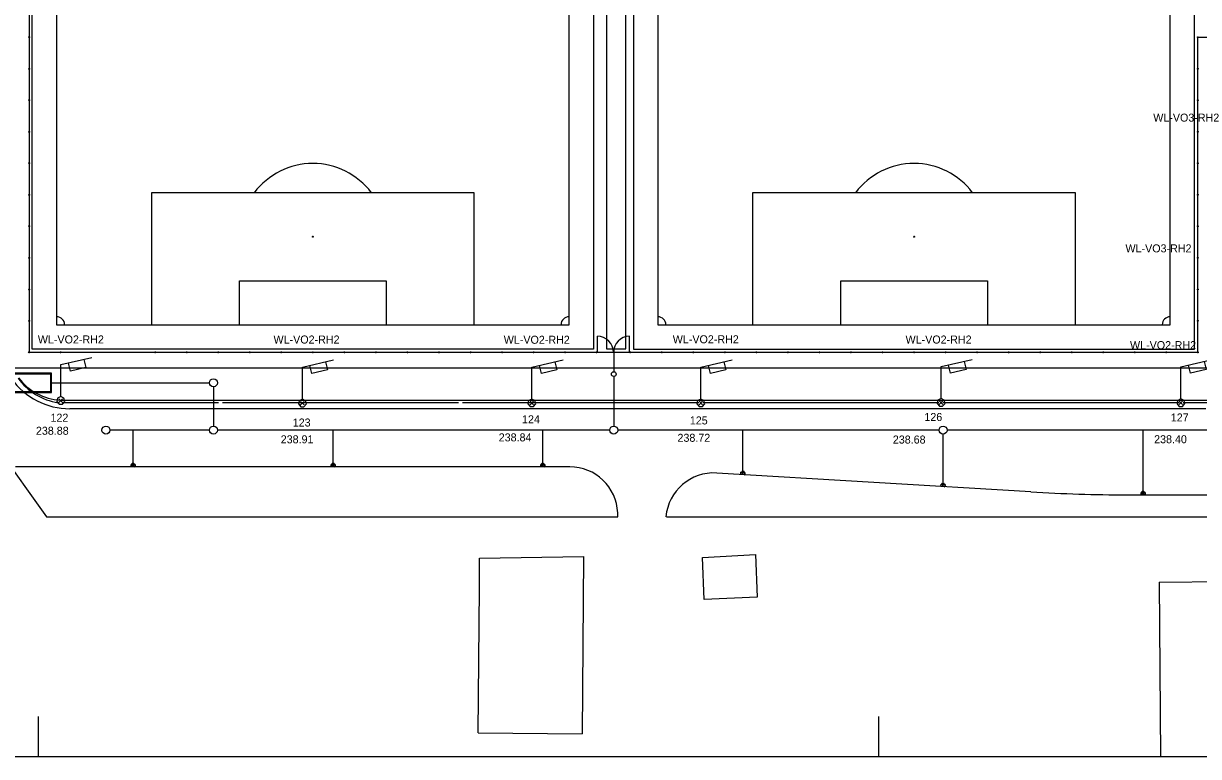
# Model space of a CAD drawing. Extents: x -264222 to -263592, y -1242345 to -1242048.
# Drawn here: x -264118.8 to -263972, y -1242344.9 to -1242253.3 of the extents above; entities that cross this region are included whole.
import ezdxf

# ---------------------------------------------------------------- set-up
doc = ezdxf.new("R2010")
doc.units = 0
for name, color, linetype in [('BOD_CISLO', 7, 'Continuous'), ('BOD_SYMBOL', 7, 'Continuous'), ('BOD_VYSKA', 7, 'Continuous'), ('KFA_2D_SITUACIA_DSP', 7, 'Continuous'), ('KFA_SO_62-1_VO_LAMPY_MERANE', 7, 'Continuous'), ('KFA_SO_62-1_VO_POPIS_LAMP_PROJEKT', 7, 'Continuous'), ('KFA_SO_62-1_VO_TRASA_KABLOV_PROJEKT', 7, 'Continuous'), ('RAM_NA_TLAC_1-500', 7, 'Continuous')]:
    doc.layers.add(name, color=color, linetype=linetype)

msp = doc.modelspace()

# ---------------------------------------------------------------- linework, layer by layer
at = {"layer": 'BOD_SYMBOL'}
for p, q in [((-264114.33, -1242300.69), (-264113.89, -1242300.25)), ((-264113.89, -1242300.69), (-264114.33, -1242300.25)), ((-264084.15, -1242301), (-264083.71, -1242300.56)), ((-264083.71, -1242301), (-264084.15, -1242300.56)), ((-264055.49, -1242300.99), (-264055.05, -1242300.55)), ((-264055.05, -1242300.99), (-264055.49, -1242300.55)), ((-264034.38, -1242300.99), (-264033.94, -1242300.54)), ((-264033.94, -1242300.99), (-264034.38, -1242300.54)), ((-264004.37, -1242300.94), (-264003.92, -1242300.5)), ((-264003.92, -1242300.94), (-264004.37, -1242300.5)), ((-263974.41, -1242300.96), (-263973.97, -1242300.52)), ((-263973.97, -1242300.96), (-263974.41, -1242300.52))]:
    msp.add_line(p, q, dxfattribs=at)
at = {"layer": 'KFA_2D_SITUACIA_DSP'}
for p, q in [((-264118.07, -1242187.53), (-264118.07, -1242294.43)), ((-264204.69, -1242191.48), (-264115.87, -1242314.98)), ((-264114.62, -1242190.98), (-264114.62, -1242290.98)), ((-264050.62, -1242290.98), (-264050.62, -1242190.98)), ((-264039.52, -1242190.98), (-264039.52, -1242290.98)), ((-263975.52, -1242290.98), (-263975.52, -1242190.98)), ((-264045.93, -1242194.98), (-264045.93, -1242293.98)), ((-264043.53, -1242293.98), (-264043.53, -1242194.98)), ((-264118.01, -1242255.06), (-264118.13, -1242255.06)), ((-264118.07, -1242255.12), (-264118.07, -1242255)), ((-263972.13, -1242255.06), (-263972.01, -1242255.06)), ((-263972.07, -1242255.12), (-263972.07, -1242255)), ((-263972.07, -1242255.06), (-263967.42, -1242255.06)), ((-263972.07, -1242294.43), (-263972.07, -1242255.06)), ((-264118.01, -1242258.99), (-264118.13, -1242258.99)), ((-264118.07, -1242259.05), (-264118.07, -1242258.93)), ((-263972.13, -1242258.99), (-263972.01, -1242258.99)), ((-263972.07, -1242259.05), (-263972.07, -1242258.93)), ((-264118.01, -1242262.93), (-264118.13, -1242262.93)), ((-264118.07, -1242262.99), (-264118.07, -1242262.87)), ((-263972.13, -1242262.93), (-263972.01, -1242262.93)), ((-263972.07, -1242262.99), (-263972.07, -1242262.87)), ((-264118.07, -1242266.93), (-264118.07, -1242266.81)), ((-263972.07, -1242266.93), (-263972.07, -1242266.81)), ((-264118.01, -1242266.87), (-264118.13, -1242266.87)), ((-263972.13, -1242266.87), (-263972.01, -1242266.87)), ((-264118.01, -1242270.81), (-264118.13, -1242270.81)), ((-264118.07, -1242270.87), (-264118.07, -1242270.75)), ((-263972.13, -1242270.81), (-263972.01, -1242270.81)), ((-263972.07, -1242270.87), (-263972.07, -1242270.75)), ((-264118.01, -1242274.74), (-264118.13, -1242274.74)), ((-264118.07, -1242274.8), (-264118.07, -1242274.68)), ((-264062.46, -1242274.48), (-264102.78, -1242274.48)), ((-264102.78, -1242274.48), (-264102.78, -1242290.98)), ((-264062.46, -1242290.98), (-264062.46, -1242274.48)), ((-263987.36, -1242274.48), (-264027.68, -1242274.48)), ((-264027.68, -1242274.48), (-264027.68, -1242290.98)), ((-263987.36, -1242290.98), (-263987.36, -1242274.48)), ((-263972.13, -1242274.74), (-263972.01, -1242274.74)), ((-263972.07, -1242274.8), (-263972.07, -1242274.68)), ((-264118.01, -1242278.68), (-264118.13, -1242278.68)), ((-264118.07, -1242278.74), (-264118.07, -1242278.62)), ((-263972.13, -1242278.68), (-263972.01, -1242278.68)), ((-263972.07, -1242278.74), (-263972.07, -1242278.62)), ((-264118.01, -1242282.62), (-264118.13, -1242282.62)), ((-264118.07, -1242282.68), (-264118.07, -1242282.56)), ((-263972.13, -1242282.62), (-263972.01, -1242282.62)), ((-263972.07, -1242282.68), (-263972.07, -1242282.56)), ((-264091.78, -1242290.98), (-264091.78, -1242285.48)), ((-264091.78, -1242285.48), (-264073.46, -1242285.48)), ((-264073.46, -1242285.48), (-264073.46, -1242290.98)), ((-264016.68, -1242290.98), (-264016.68, -1242285.48)), ((-264016.68, -1242285.48), (-263998.36, -1242285.48)), ((-263998.36, -1242285.48), (-263998.36, -1242290.98)), ((-264118.01, -1242286.56), (-264118.13, -1242286.56)), ((-264118.07, -1242286.62), (-264118.07, -1242286.5)), ((-263972.13, -1242286.56), (-263972.01, -1242286.56)), ((-263972.07, -1242286.62), (-263972.07, -1242286.5)), ((-264118.01, -1242290.49), (-264118.13, -1242290.49)), ((-264118.07, -1242290.55), (-264118.07, -1242290.43)), ((-264114.62, -1242290.98), (-264050.62, -1242290.98)), ((-264039.52, -1242290.98), (-263975.52, -1242290.98)), ((-263972.13, -1242290.49), (-263972.01, -1242290.49)), ((-263972.07, -1242290.55), (-263972.07, -1242290.43)), ((-264047.07, -1242294.43), (-264047.07, -1242292.43)), ((-264043.07, -1242294.43), (-264043.07, -1242292.43)), ((-264118.01, -1242294.43), (-264118.13, -1242294.43)), ((-264118.07, -1242294.49), (-264118.07, -1242294.37)), ((-264118.07, -1242294.43), (-264045.12, -1242294.43)), ((-264114.07, -1242294.43), (-264114.19, -1242294.43)), ((-264114.13, -1242294.49), (-264114.13, -1242294.37)), ((-264102.25, -1242294.43), (-264102.37, -1242294.43)), ((-264102.31, -1242294.49), (-264102.31, -1242294.37)), ((-264098.31, -1242294.43), (-264098.43, -1242294.43)), ((-264098.37, -1242294.49), (-264098.37, -1242294.37)), ((-264094.37, -1242294.43), (-264094.49, -1242294.43)), ((-264094.43, -1242294.49), (-264094.43, -1242294.37)), ((-264090.44, -1242294.43), (-264090.56, -1242294.43)), ((-264090.5, -1242294.49), (-264090.5, -1242294.37)), ((-264086.5, -1242294.43), (-264086.62, -1242294.43)), ((-264086.56, -1242294.49), (-264086.56, -1242294.37)), ((-264082.56, -1242294.43), (-264082.68, -1242294.43)), ((-264082.62, -1242294.49), (-264082.62, -1242294.37)), ((-264078.62, -1242294.43), (-264078.74, -1242294.43)), ((-264078.68, -1242294.49), (-264078.68, -1242294.37)), ((-264074.68, -1242294.43), (-264074.8, -1242294.43)), ((-264074.74, -1242294.49), (-264074.74, -1242294.37)), ((-264070.74, -1242294.43), (-264070.86, -1242294.43)), ((-264070.8, -1242294.49), (-264070.8, -1242294.37)), ((-264066.8, -1242294.43), (-264066.92, -1242294.43)), ((-264066.86, -1242294.49), (-264066.86, -1242294.37)), ((-264062.86, -1242294.43), (-264062.98, -1242294.43)), ((-264062.92, -1242294.49), (-264062.92, -1242294.37)), ((-264058.92, -1242294.43), (-264059.04, -1242294.43)), ((-264058.98, -1242294.49), (-264058.98, -1242294.37)), ((-264054.99, -1242294.43), (-264055.11, -1242294.43)), ((-264055.05, -1242294.49), (-264055.05, -1242294.37)), ((-264051.05, -1242294.43), (-264051.17, -1242294.43)), ((-264051.11, -1242294.49), (-264051.11, -1242294.37)), ((-264047.11, -1242294.43), (-264047.23, -1242294.43)), ((-264047.17, -1242294.49), (-264047.17, -1242294.37)), ((-264045.93, -1242293.98), (-264043.53, -1242293.98)), ((-264045.57, -1242294.43), (-264044.57, -1242294.43)), ((-264045.12, -1242294.43), (-263972.07, -1242294.43)), ((-264045.02, -1242293.98), (-264045.03, -1242296.85)), ((-264042.91, -1242294.43), (-264043.03, -1242294.43)), ((-264042.97, -1242294.49), (-264042.97, -1242294.37)), ((-264038.97, -1242294.43), (-264039.09, -1242294.43)), ((-264039.03, -1242294.49), (-264039.03, -1242294.37)), ((-264035.03, -1242294.43), (-264035.15, -1242294.43)), ((-264035.09, -1242294.49), (-264035.09, -1242294.37)), ((-264031.09, -1242294.43), (-264031.21, -1242294.43)), ((-264031.15, -1242294.49), (-264031.15, -1242294.37)), ((-264027.15, -1242294.43), (-264027.27, -1242294.43)), ((-264027.21, -1242294.49), (-264027.21, -1242294.37)), ((-264023.21, -1242294.43), (-264023.33, -1242294.43)), ((-264023.27, -1242294.49), (-264023.27, -1242294.37)), ((-264019.27, -1242294.43), (-264019.39, -1242294.43)), ((-264019.33, -1242294.49), (-264019.33, -1242294.37)), ((-264015.34, -1242294.43), (-264015.46, -1242294.43)), ((-264015.4, -1242294.49), (-264015.4, -1242294.37)), ((-264011.4, -1242294.43), (-264011.52, -1242294.43)), ((-264011.46, -1242294.49), (-264011.46, -1242294.37)), ((-264007.46, -1242294.43), (-264007.58, -1242294.43)), ((-264007.52, -1242294.49), (-264007.52, -1242294.37)), ((-264003.52, -1242294.43), (-264003.64, -1242294.43)), ((-264003.58, -1242294.49), (-264003.58, -1242294.37)), ((-263999.58, -1242294.43), (-263999.7, -1242294.43)), ((-263999.64, -1242294.49), (-263999.64, -1242294.37)), ((-263995.64, -1242294.43), (-263995.76, -1242294.43)), ((-263995.7, -1242294.49), (-263995.7, -1242294.37)), ((-263991.7, -1242294.43), (-263991.82, -1242294.43)), ((-263991.76, -1242294.49), (-263991.76, -1242294.37)), ((-263987.76, -1242294.43), (-263987.88, -1242294.43)), ((-263987.82, -1242294.49), (-263987.82, -1242294.37)), ((-263983.82, -1242294.43), (-263983.94, -1242294.43)), ((-263983.88, -1242294.49), (-263983.88, -1242294.37)), ((-263979.89, -1242294.43), (-263980.01, -1242294.43)), ((-263979.95, -1242294.49), (-263979.95, -1242294.37)), ((-263975.95, -1242294.43), (-263976.07, -1242294.43)), ((-263976.01, -1242294.49), (-263976.01, -1242294.37)), ((-263972.13, -1242294.43), (-263972.01, -1242294.43)), ((-263972.07, -1242294.49), (-263972.07, -1242294.37)), ((-264115.25, -1242297.04), (-264120.15, -1242297.04)), ((-264115.35, -1242297.14), (-264120.05, -1242297.14)), ((-264115.35, -1242299.34), (-264115.35, -1242297.14)), ((-264115.25, -1242299.44), (-264115.25, -1242297.04)), ((-264045.03, -1242297.45), (-264045.03, -1242303.65)), ((-264115.25, -1242298.24), (-264095.53, -1242298.24)), ((-264095.03, -1242298.74), (-264095.03, -1242303.65)), ((-264120.15, -1242299.44), (-264115.25, -1242299.44)), ((-264120.05, -1242299.34), (-264115.35, -1242299.34)), ((-263971.07, -1242301.48), (-264112.96, -1242301.48)), ((-264095.53, -1242304.15), (-264107.96, -1242304.15)), ((-264105.08, -1242308.24), (-264105.08, -1242304.15)), ((-264045.53, -1242304.15), (-264094.53, -1242304.15)), ((-264080.08, -1242308.24), (-264080.08, -1242304.15)), ((-264053.91, -1242308.24), (-264053.91, -1242304.15)), ((-264004.4, -1242304.15), (-264044.53, -1242304.15)), ((-264028.9, -1242309.22), (-264028.89, -1242304.15)), ((-264003.9, -1242310.72), (-264003.9, -1242304.65)), ((-263954.41, -1242304.15), (-264003.4, -1242304.15)), ((-263978.91, -1242311.74), (-263978.91, -1242304.15)), ((-264050.53, -1242308.73), (-264119.75, -1242308.73)), ((-264105.33, -1242308.44), (-264104.83, -1242308.44)), ((-264105.33, -1242308.73), (-264105.33, -1242308.44)), ((-264105.33, -1242308.44), (-264104.83, -1242308.73)), ((-264105.33, -1242308.44), (-264104.83, -1242308.73)), ((-264104.83, -1242308.44), (-264105.33, -1242308.44)), ((-264104.83, -1242308.73), (-264105.33, -1242308.73)), ((-264104.83, -1242308.44), (-264104.83, -1242308.73)), ((-264104.83, -1242308.73), (-264104.83, -1242308.44)), ((-264080.33, -1242308.44), (-264079.83, -1242308.44)), ((-264080.33, -1242308.73), (-264080.33, -1242308.44)), ((-264080.33, -1242308.44), (-264079.83, -1242308.73)), ((-264080.33, -1242308.44), (-264079.83, -1242308.73)), ((-264079.83, -1242308.44), (-264080.33, -1242308.44)), ((-264079.83, -1242308.73), (-264080.33, -1242308.73)), ((-264079.83, -1242308.44), (-264079.83, -1242308.73)), ((-264079.83, -1242308.73), (-264079.83, -1242308.44)), ((-264054.16, -1242308.44), (-264053.66, -1242308.44)), ((-264054.16, -1242308.73), (-264054.16, -1242308.44)), ((-264054.16, -1242308.44), (-264053.66, -1242308.73)), ((-264054.16, -1242308.44), (-264053.66, -1242308.73)), ((-264053.66, -1242308.44), (-264054.16, -1242308.44)), ((-264053.66, -1242308.73), (-264054.16, -1242308.73)), ((-264053.66, -1242308.44), (-264053.66, -1242308.73)), ((-264053.66, -1242308.73), (-264053.66, -1242308.44)), ((-263992.94, -1242311.87), (-264032.17, -1242309.51)), ((-264032.17, -1242309.51), (-264032.17, -1242309.51)), ((-264029.16, -1242309.69), (-264029.14, -1242309.41)), ((-264028.66, -1242309.72), (-264029.16, -1242309.69)), ((-264029.14, -1242309.41), (-264028.65, -1242309.44)), ((-264029.14, -1242309.41), (-264028.66, -1242309.72)), ((-264029.14, -1242309.41), (-264028.66, -1242309.72)), ((-264028.65, -1242309.44), (-264029.14, -1242309.41)), ((-264028.65, -1242309.44), (-264028.66, -1242309.72)), ((-264028.66, -1242309.72), (-264028.65, -1242309.44)), ((-264004.16, -1242311.2), (-264004.15, -1242310.91)), ((-264003.66, -1242311.23), (-264004.16, -1242311.2)), ((-264004.15, -1242310.91), (-264003.65, -1242310.94)), ((-264004.15, -1242310.91), (-264003.66, -1242311.23)), ((-264004.15, -1242310.91), (-264003.66, -1242311.23)), ((-264003.65, -1242310.94), (-264004.15, -1242310.91)), ((-264003.65, -1242310.94), (-264003.66, -1242311.23)), ((-264003.66, -1242311.23), (-264003.65, -1242310.94)), ((-263980.94, -1242312.23), (-263857.33, -1242312.23)), ((-263979.16, -1242311.94), (-263978.66, -1242311.94)), ((-263979.16, -1242312.23), (-263979.16, -1242311.94)), ((-263979.16, -1242311.94), (-263978.66, -1242312.23)), ((-263979.16, -1242311.94), (-263978.66, -1242312.23)), ((-263978.66, -1242311.94), (-263979.16, -1242311.94)), ((-263978.66, -1242312.23), (-263979.16, -1242312.23)), ((-263978.66, -1242311.94), (-263978.66, -1242312.23)), ((-263978.66, -1242312.23), (-263978.66, -1242311.94)), ((-264115.89, -1242314.98), (-264044.53, -1242314.98)), ((-264044.53, -1242314.98), (-264044.53, -1242314.48)), ((-264038.44, -1242314.98), (-263836.4, -1242314.98)), ((-264061.82, -1242323.92), (-264061.79, -1242320.14)), ((-264061.79, -1242320.14), (-264048.82, -1242319.93)), ((-264048.82, -1242319.93), (-264048.99, -1242342.09)), ((-264033.95, -1242320.06), (-264027.34, -1242319.71)), ((-264033.72, -1242325.32), (-264033.95, -1242320.06)), ((-264027.34, -1242319.71), (-264027.11, -1242325.04)), ((-263976.89, -1242323.14), (-263880.39, -1242322.51)), ((-264061.96, -1242341.99), (-264061.82, -1242323.92)), ((-263976.89, -1242323.14), (-263976.75, -1242344.94)), ((-264027.11, -1242325.04), (-264033.72, -1242325.32)), ((-264061.96, -1242341.99), (-264048.99, -1242342.09))]:
    msp.add_line(p, q, dxfattribs=at)
for points in [[(-264117.67, -1242187.93), (-264047.57, -1242187.93), (-264047.57, -1242294.03), (-264117.67, -1242294.03)], [(-264042.57, -1242294.03), (-263972.47, -1242294.03), (-263972.47, -1242187.93), (-264042.57, -1242187.93)]]:
    msp.add_lwpolyline(points, close=True, dxfattribs=at)
msp.add_lwpolyline([(-263965.14, -1242296.43), (-264120.02, -1242296.43), (-264120.28, -1242296.43)], dxfattribs=at)
for centre, radius in [((-264118.07, -1242255.06), 0.06), ((-263972.07, -1242255.06), 0.06), ((-264118.07, -1242258.99), 0.06), ((-263972.07, -1242258.99), 0.06), ((-264118.07, -1242262.93), 0.06), ((-263972.07, -1242262.93), 0.06), ((-264118.07, -1242266.87), 0.06), ((-263972.07, -1242266.87), 0.06), ((-264118.07, -1242270.81), 0.06), ((-263972.07, -1242270.81), 0.06), ((-264118.07, -1242274.74), 0.06), ((-263972.07, -1242274.74), 0.06), ((-264118.07, -1242278.68), 0.06), ((-264082.62, -1242279.98), 0.06), ((-264007.52, -1242279.98), 0.06), ((-263972.07, -1242278.68), 0.06), ((-264118.07, -1242282.62), 0.06), ((-263972.07, -1242282.62), 0.06), ((-264118.07, -1242286.56), 0.06), ((-263972.07, -1242286.56), 0.06), ((-264118.07, -1242290.49), 0.06), ((-263972.07, -1242290.49), 0.06), ((-264118.07, -1242294.43), 0.06), ((-264114.13, -1242294.43), 0.06), ((-264102.31, -1242294.43), 0.06), ((-264098.37, -1242294.43), 0.06), ((-264094.43, -1242294.43), 0.06), ((-264090.5, -1242294.43), 0.06), ((-264086.56, -1242294.43), 0.06), ((-264082.62, -1242294.43), 0.06), ((-264078.68, -1242294.43), 0.06), ((-264074.74, -1242294.43), 0.06), ((-264070.8, -1242294.43), 0.06), ((-264066.86, -1242294.43), 0.06), ((-264062.92, -1242294.43), 0.06), ((-264058.98, -1242294.43), 0.06), ((-264055.05, -1242294.43), 0.06), ((-264051.11, -1242294.43), 0.06), ((-264047.17, -1242294.43), 0.06), ((-264042.97, -1242294.43), 0.06), ((-264039.03, -1242294.43), 0.06), ((-264035.09, -1242294.43), 0.06), ((-264031.15, -1242294.43), 0.06), ((-264027.21, -1242294.43), 0.06), ((-264023.27, -1242294.43), 0.06), ((-264019.33, -1242294.43), 0.06), ((-264015.4, -1242294.43), 0.06), ((-264011.46, -1242294.43), 0.06), ((-264007.52, -1242294.43), 0.06), ((-264003.58, -1242294.43), 0.06), ((-263999.64, -1242294.43), 0.06), ((-263995.7, -1242294.43), 0.06), ((-263991.76, -1242294.43), 0.06), ((-263987.82, -1242294.43), 0.06), ((-263983.88, -1242294.43), 0.06), ((-263979.95, -1242294.43), 0.06), ((-263976.01, -1242294.43), 0.06), ((-263972.07, -1242294.43), 0.06), ((-264045.03, -1242297.15), 0.3), ((-264095.03, -1242298.24), 0.5), ((-264108.46, -1242304.15), 0.5), ((-264095.03, -1242304.15), 0.5), ((-264045.03, -1242304.15), 0.5), ((-264003.9, -1242304.15), 0.5), ((-264105.08, -1242308.34), 0.1), ((-264080.08, -1242308.34), 0.1), ((-264053.91, -1242308.34), 0.1), ((-264028.89, -1242309.32), 0.1), ((-264003.9, -1242310.82), 0.1), ((-263978.91, -1242311.84), 0.1)]:
    msp.add_circle(centre, radius, dxfattribs=at)
for centre, radius, start, end in [((-264082.62, -1242279.98), 9.15, 36.9482, 143.0518), ((-264007.52, -1242279.98), 9.15, 36.9482, 143.0518), ((-264082.62, -1242279.98), 0.0303, 90, 270), ((-264082.62, -1242279.98), 0.0303, 270, 90), ((-264007.52, -1242279.98), 0.0303, 90, 270), ((-264007.52, -1242279.98), 0.0303, 270, 90), ((-264114.62, -1242290.98), 1, 0, 90), ((-264050.62, -1242290.98), 1, 90, 180), ((-264039.52, -1242290.98), 1, 0, 90), ((-263975.52, -1242290.98), 1, 90, 180), ((-264047.07, -1242294.43), 2, 0, 90), ((-264043.07, -1242294.43), 2, 90, 180), ((-264112.96, -1242292.48), 9, 215.724, 270), ((-264050.56, -1242314.77), 6.04, 2.7254, 89.7124), ((-264032.53, -1242315.5), 6, 86.5602, 175.0205), ((-263980.94, -1242112.23), 200, 266.5602, 270)]:
    msp.add_arc(centre, radius, start, end, dxfattribs=at)
at = {"layer": 'KFA_SO_62-1_VO_LAMPY_MERANE'}
for p, q in [((-264114.16, -1242300.47), (-264114.06, -1242300.47)), ((-264114.11, -1242300.47), (-264114.11, -1242300.47)), ((-264083.98, -1242300.78), (-264083.88, -1242300.78)), ((-264083.93, -1242300.78), (-264083.93, -1242300.78)), ((-264055.32, -1242300.77), (-264055.22, -1242300.77)), ((-264055.27, -1242300.77), (-264055.27, -1242300.77)), ((-264034.21, -1242300.77), (-264034.11, -1242300.77)), ((-264034.16, -1242300.77), (-264034.16, -1242300.77)), ((-264004.2, -1242300.72), (-264004.1, -1242300.72)), ((-264004.15, -1242300.72), (-264004.15, -1242300.72)), ((-263974.24, -1242300.74), (-263974.14, -1242300.74)), ((-263974.19, -1242300.74), (-263974.19, -1242300.74))]:
    msp.add_line(p, q, dxfattribs=at)
for points in [[(-264114.11, -1242299.97), (-264114.51, -1242300.17), (-264114.61, -1242300.57), (-264114.31, -1242300.92), (-264113.91, -1242300.92), (-264113.61, -1242300.57), (-264113.71, -1242300.17), (-264114.11, -1242299.97), (-264114.11, -1242295.97), (-264110.21, -1242295.07)], [(-264111.21, -1242295.32), (-264110.96, -1242296.32), (-264112.91, -1242296.77), (-264113.16, -1242295.77)], [(-264083.93, -1242300.28), (-264084.33, -1242300.48), (-264084.43, -1242300.88), (-264084.13, -1242301.23), (-264083.73, -1242301.23), (-264083.43, -1242300.88), (-264083.53, -1242300.48), (-264083.93, -1242300.28), (-264083.93, -1242296.28), (-264080.03, -1242295.38)], [(-264081.03, -1242295.63), (-264080.78, -1242296.63), (-264082.73, -1242297.08), (-264082.98, -1242296.08)], [(-264055.27, -1242300.27), (-264055.67, -1242300.47), (-264055.77, -1242300.87), (-264055.47, -1242301.22), (-264055.07, -1242301.22), (-264054.77, -1242300.87), (-264054.87, -1242300.47), (-264055.27, -1242300.27), (-264055.27, -1242296.27), (-264051.37, -1242295.37)], [(-264052.37, -1242295.62), (-264052.12, -1242296.62), (-264054.07, -1242297.07), (-264054.32, -1242296.07)], [(-264034.16, -1242300.27), (-264034.56, -1242300.47), (-264034.66, -1242300.87), (-264034.36, -1242301.22), (-264033.96, -1242301.22), (-264033.66, -1242300.87), (-264033.76, -1242300.47), (-264034.16, -1242300.27), (-264034.16, -1242296.27), (-264030.26, -1242295.37)], [(-264031.26, -1242295.62), (-264031.01, -1242296.62), (-264032.96, -1242297.07), (-264033.21, -1242296.07)], [(-264004.15, -1242300.22), (-264004.54, -1242300.42), (-264004.65, -1242300.82), (-264004.35, -1242301.17), (-264003.95, -1242301.17), (-264003.65, -1242300.82), (-264003.74, -1242300.42), (-264004.15, -1242300.22), (-264004.15, -1242296.22), (-264000.24, -1242295.32)], [(-264001.24, -1242295.57), (-264000.99, -1242296.57), (-264002.95, -1242297.02), (-264003.2, -1242296.02)], [(-263974.19, -1242300.24), (-263974.59, -1242300.44), (-263974.69, -1242300.84), (-263974.39, -1242301.19), (-263973.99, -1242301.19), (-263973.69, -1242300.84), (-263973.79, -1242300.44), (-263974.19, -1242300.24), (-263974.19, -1242296.24), (-263970.29, -1242295.34)], [(-263971.29, -1242295.59), (-263971.04, -1242296.59), (-263972.99, -1242297.04), (-263973.24, -1242296.04)]]:
    msp.add_lwpolyline(points, dxfattribs=at)
at = {"layer": 'KFA_SO_62-1_VO_TRASA_KABLOV_PROJEKT'}
for p, q in [((-264114.14, -1242300.4), (-263918.84, -1242300.4)), ((-264094.42, -1242300.74), (-264113.92, -1242300.74)), ((-264064.42, -1242300.74), (-264093.92, -1242300.74)), ((-264034.42, -1242300.74), (-264063.92, -1242300.74)), ((-264004.42, -1242300.74), (-264033.92, -1242300.74)), ((-263974.42, -1242300.74), (-264003.92, -1242300.74)), ((-263944.42, -1242300.74), (-263973.92, -1242300.74))]:
    msp.add_line(p, q, dxfattribs=at)
for centre, radius, start, end in [((-264113.76, -1242293.36), 7.05, 216.9801, 266.8749), ((-264113.25, -1242293.18), 7.64, 215.7871, 261.1375)]:
    msp.add_arc(centre, radius, start, end, dxfattribs=at)
at = {"layer": 'RAM_NA_TLAC_1-500'}
for p, q in [((-264116.9, -1242344.94), (-264116.9, -1242339.94)), ((-264011.9, -1242344.94), (-264011.9, -1242339.94))]:
    msp.add_line(p, q, dxfattribs=at)
msp.add_lwpolyline([(-264221.9, -1242344.94), (-263591.9, -1242344.94), (-263591.9, -1242047.94), (-264221.9, -1242047.94)], close=True, dxfattribs=at)

# ---------------------------------------------------------------- texts
at = {"layer": 'BOD_CISLO'}
for s, p in [('126', (-264006.23, -1242303.01)), ('122', (-264115.39, -1242303.1)), ('123', (-264085.13, -1242303.7)), ('124', (-264056.49, -1242303.3)), ('125', (-264035.53, -1242303.44)), ('127', (-263975.45, -1242303.07))]:
    msp.add_text(s, height=1, dxfattribs=at).set_placement(p)
at = {"layer": 'BOD_VYSKA'}
for s, p in [('238.88', (-264117.21, -1242304.73)), ('238.91', (-264086.63, -1242305.8)), ('238.84', (-264059.4, -1242305.56)), ('238.72', (-264037.07, -1242305.61)), ('238.68', (-264010.17, -1242305.83)), ('238.40', (-263977.53, -1242305.79))]:
    msp.add_text(s, height=1, dxfattribs=at).set_placement(p)
at = {"layer": 'KFA_SO_62-1_VO_POPIS_LAMP_PROJEKT'}
for s, p in [('WL-VO3-RH2', (-263977.64, -1242265.6)), ('WL-VO3-RH2', (-263981.11, -1242281.94)), ('WL-VO2-RH2', (-264116.97, -1242293.32)), ('WL-VO2-RH2', (-264087.53, -1242293.33)), ('WL-VO2-RH2', (-264058.77, -1242293.36)), ('WL-VO2-RH2', (-264037.66, -1242293.3)), ('WL-VO2-RH2', (-264008.58, -1242293.33)), ('WL-VO2-RH2', (-263980.54, -1242294.03))]:
    msp.add_text(s, height=1, dxfattribs=at).set_placement(p)

doc.saveas('drawing.dxf')
